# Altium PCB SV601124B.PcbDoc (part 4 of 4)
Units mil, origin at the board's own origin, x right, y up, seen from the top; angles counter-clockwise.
Board outline 3733 x 2734 mil, 4 copper layers (Top Layer, Mid-Layer 1, Mid-Layer 2, Bottom Layer), stack 60.2 mil thick; 246 components, 169 nets, 780 pads, 426 vias.
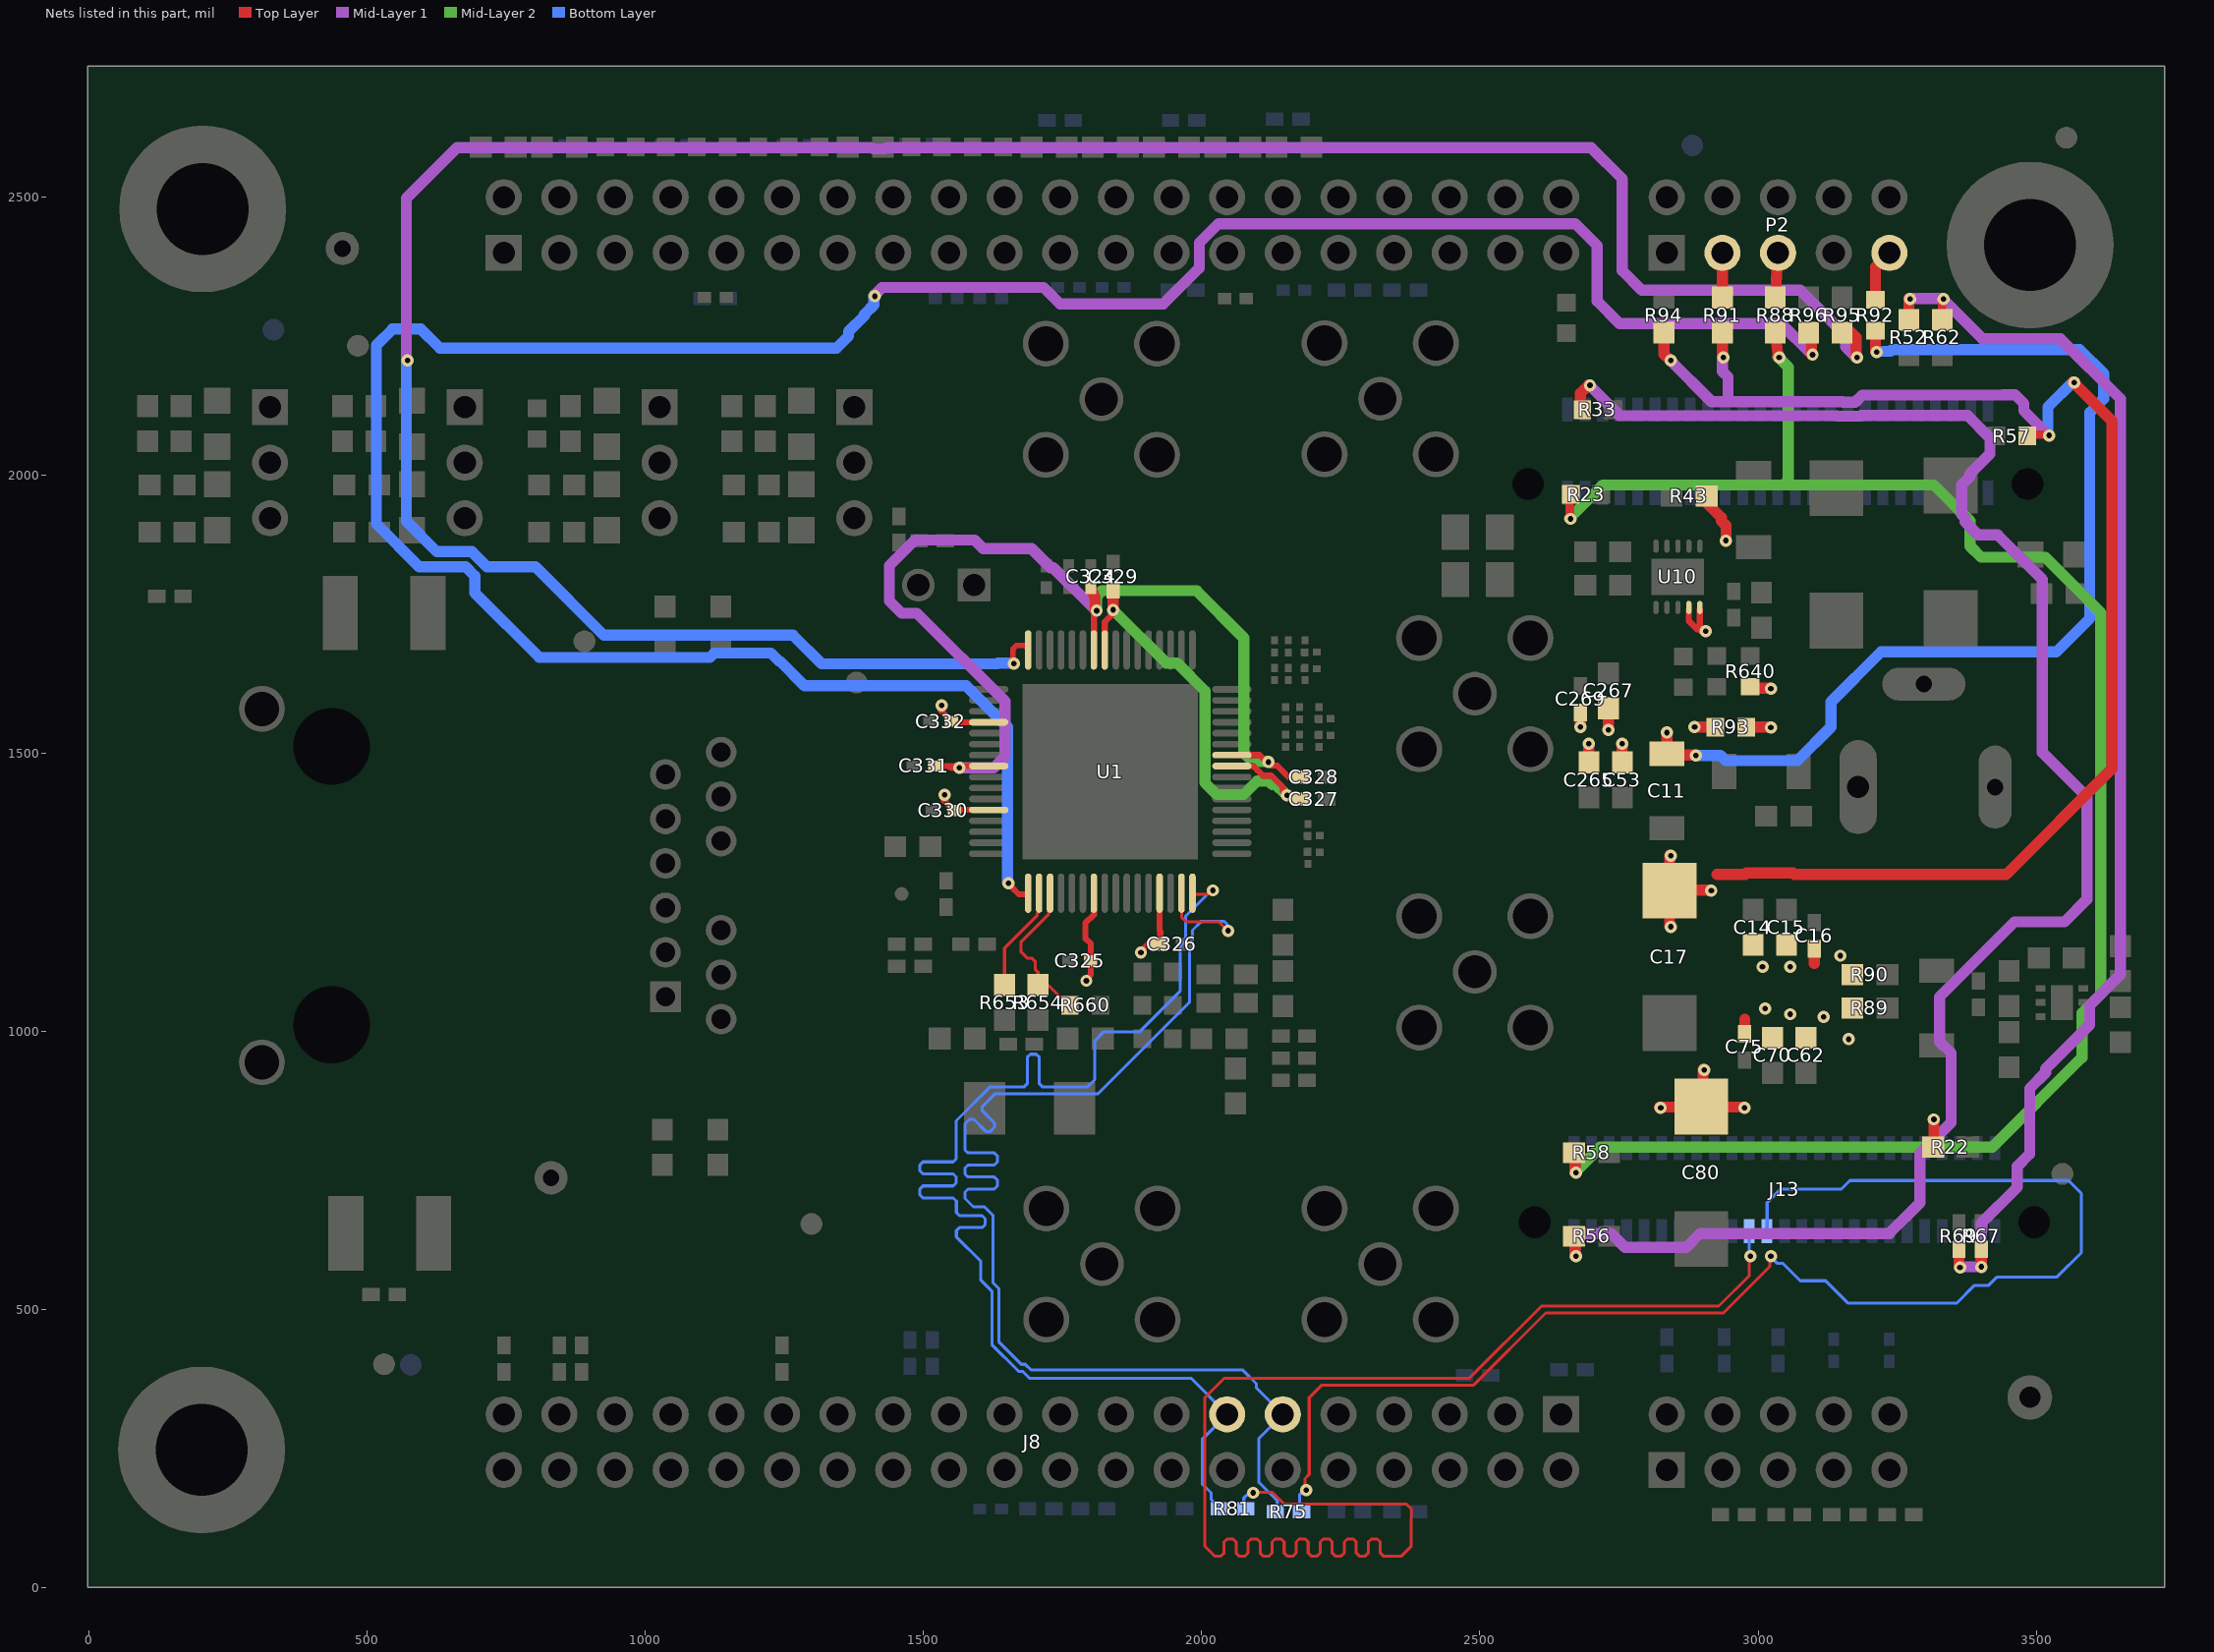
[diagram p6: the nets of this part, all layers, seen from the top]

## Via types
v1: diameter 22, hole 10, Top Layer to Bottom Layer, 385 vias
v2: diameter 19.68, hole 7.87, Top Layer to Bottom Layer, 40 vias
v3: diameter 20, hole 10, Top Layer to Bottom Layer, 1 vias

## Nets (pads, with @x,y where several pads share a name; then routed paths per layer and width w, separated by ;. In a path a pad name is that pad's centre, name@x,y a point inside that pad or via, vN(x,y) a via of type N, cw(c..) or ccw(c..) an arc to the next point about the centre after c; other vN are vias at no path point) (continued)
TXD6: J8.13 R81.1 U1.32 | length 2320.9
  Top Layer w5.4: U1.32@1983.6,1246.46 2010.46,1246.46 v1@2018.46,1254.46
  Bottom Layer w5.4: v1@2018.46,1254.46 1971.3,1207.3 1971.3,1162.86 1961.3,1152.86 1961.3,1072.14 1888.56,999.4 1824.44,999.4 1808.04,983 1808.04,913.26 1795.38,900.6 1713.79,900.6 1708.39,906 1708.39,953.6 1702.99,959 1692.19,959 1686.79,953.6 1686.79,906 1681.39,900.6 1620.38,900.6 1559,839.22 1559,771 1553.6,765.6 1499.4,765.6 1494,760.2 1494,749.4 1499.4,744 1553.6,744 1559,738.6 1559,727.8 1553.6,722.4 1499.4,722.4 1494,717 1494,706.2 1499.4,700.8 1553.6,700.8 1559,695.4 1559.4,695.4 1559.4,674.48 1564.8,669.08 1605.6,669.08 1611,663.68 1611,652.88 1605.6,647.48 1564.8,647.48 1559.4,642.08 1559.4,630.68 1603.4,586.68 1603.4,552.98 1623.1,533.28 1623.1,437.44 1671.11,389.43 1678.09,389.43 1690.49,377.03 1980.97,377.03 J8.13@2046,312 2001,267 2001,187 2017.14,170.86 2017.14,158.86 2034,142 R81.1@2036,142
  other v1: 2020.46,1253.46
TXD6_EMB: J13.30 R81.2 | length 2545.7
  Top Layer w5.4: v1@2091,172 2127,172 2148.34,150.66 2368.46,150.66 2377,142.12 2377,75 2359.4,57.4 2326.6,57.4 2321.2,62.8 2321.2,82.6 2315.8,88 2305,88 2299.6,82.6 2299.6,62.8 2294.2,57.4 2283.4,57.4 2278,62.8 2278,82.6 2272.6,88 2261.8,88 2256.4,82.6 2256.4,62.8 2251,57.4 2240.2,57.4 2234.8,62.8 2234.8,82.6 2229.4,88 2218.6,88 2213.2,82.6 2213.2,62.8 2207.8,57.4 2197,57.4 2191.6,62.8 2191.6,82.6 2186.2,88 2175.4,88 2170,82.6 2170,62.8 2164.6,57.4 2153.8,57.4 2148.4,62.8 2148.4,82.6 2143,88 2132.2,88 2126.8,82.6 2126.8,62.8 2121.4,57.4 2110.6,57.4 2105.2,62.8 2105.2,82.6 2099.8,88 2089,88 2083.6,82.6 2083.6,62.8 2078.2,57.4 2067.4,57.4 2062,62.8 2062,82.6 2056.6,88 2045.8,88 2040.4,82.6 2040.4,62.8 2035,57.4 2023.6,57.4 2005.77,75.23 2005.77,341.77 2041.03,377.03 2481.42,377.03 2610.89,506.5 2929.5,506.5 2984.36,561.36 v1@2984.36,597
  Bottom Layer w5.4: R81.2@2076,142 2076,161.7 2086.3,172 v1@2091,172 ; v1@2984.36,597 J13.30@2984.36,640.8
  other v1: 2093,171 2986.36,596
TXD7: J8.11 R75.1 U1.31 | length 2321
  Top Layer w5.4: U1.31@1963.92,1246.46 1963.92,1205.4 1972.32,1197 2031,1197 v1@2046,1182
  Bottom Layer w5.4: v1@2046,1182 2046,1192.62 2041,1197.62 1999.32,1197.62 1983.7,1182 1983.7,1151.17 1978.46,1145.93 1978.46,1052.46 1814.2,888.2 1629.2,888.2 1606,865 1606,857.38 1627.88,835.5 1627.88,827.88 1620.22,820.22 1612.6,820.22 1590.72,842.1 1583.1,842.1 1575,834 1575,787 1580.4,781.6 1627.6,781.6 1633,776.2 1633,765.4 1627.6,760 1580.4,760 1575,754.6 1575,743.8 1580.4,738.4 1627.6,738.4 1633,733 1633,722.2 1627.6,716.8 1580.4,716.8 1575,711.4 1575,700 1590,685 1610,685 1625,670 1625,548.92 1635.5,538.42 1635.5,442.58 1676.25,401.83 1683.23,401.83 1693.06,392 2073.54,392 2098.63,366.91 2098.63,359.37 J8.11@2146,312 2103.14,269.14 2103.14,189.56 2136,156.7 R75.1@2136,137
  other v1: 2048,1181
TXD7_EMB: J13.28 R75.2 | length 2538.9
  Top Layer w5.4: v1@2186,177 2186,196.7 2193.37,204.07 2193.37,341.91 2216.09,364.63 2489.13,364.63 2618.6,494.1 2937.8,494.1 3021,577.3 v1@3021,597
  Bottom Layer w5.4: R75.2@2176,137 2176,167 v1@2186,177 ; J13.28@3016.36,640.8 3016.36,692.36 3041,717 3150,717 3165.08,732.08 3557.92,732.08 3581,709 3581,602.46 3537.44,558.9 3429.72,558.9 3414.72,543.9 3389.12,543.9 3356.62,511.4 3162.14,511.4 3121.54,552 3076,552 3044.94,583.06 3034.94,583.06 v1@3021,597
  other v1: 2188,176 3023,596
UN-USED_SUPPLY_3V3: R33.2 R56.1 | length 3248.7
  Top Layer w20: v1@2671,597 R56.1@2671,632 ; R33.2@2681,2117 2681,2147 v1@2696,2162
  Mid-Layer 1 w20: v1@2671,597 2671,627 2681,637 2736,637 2761,612 2871,612 2896,637 3236,637 3291,692 3291,780.22 3347,836.22 3347,961 3326,982 3326,1062 3461,1197 3550.64,1197 3591,1237.36 3591,1421 3511,1501 3511,1812 3431,1892 3396,1892 3372,1916 3372,1922.78 3366,1928.78 3366,1982 3381,1997 3381,2002 3416.86,2037.86 3416.86,2066.14 3376,2107 3186.12,2107 3184.67,2105.55 3142.43,2105.55 3141.43,2106.55 2935.64,2106.55 2751.45,2106.55 v1@2696,2162
  other v1: 2673,596 2698,2161
VDD1P1: R52.2 R62.2 R67.1 R69.1 | length 2306.6
  Top Layer w15: R62.2@3331,2277 v1@3331,2317
  Top Layer w20: R52.2@3271,2278.5 v1@3271,2317 ; v1@3361,577 R69.1@3361,612 ; v1(3401,577) R67.1@3401,612
  Mid-Layer 1 w20: v1@3271,2317 3331,2317 3403.29,2244.71 3543.29,2244.71 3651,2137 3651,1102 3596,1047 3596,1012 3517,933 3517,926.22 3488.2,897.42 3488.2,780.02 3466,757.82 3466,720.22 3401,655.22 v1(3401,577) v1@3361,577
  other v1: 3363,576 3273,2316 3333,2316
VDDA1P8_AB: R95.1 U1.64 | length 4806.5
  Top Layer w10: v1@1661,1662 1661,1687 1667.89,1693.89 1682.05,1693.89 U1.64@1688.4,1687.54
  Top Layer w20: R95.1@3151,2257 3166,2257 3176,2247 v1@3176,2212
  Mid-Layer 1 w20: v1@571,2207 571,2497 662,2588 1404.55,2588 1408.16,2587.43 1411.86,2586.07 1412.46,2585.7 1429.44,2585.7 1433.08,2587.21 1436.94,2587.98 2700,2587.98 2755.98,2532 2755.98,2367 2790.99,2331.99 3075.99,2331.99 3157.61,2250.37 3157.61,2230.39 v1@3176,2212
  Bottom Layer w20: v1@571,2207 571,1917 625.99,1862 688.79,1862 715.79,1835 803,1835 926,1712 1266,1712 1317.56,1660.44 1632.44,1660.44 1634,1662 v1@1661,1662
  other v1: 1663,1661 573,2206 3178,2211
VDDA1P8_CD: R96.1 U1.17 | length 4919
  Top Layer w10: 1663.54,1254.46 1671.54,1246.46 U1.17@1688.4,1246.46
  Top Layer w11: v1@1651,1267 1663.54,1254.46
  Top Layer w20: R96.1@3091,2257 3095.29,2252.71 3096,2247 v1@3096,2217
  Mid-Layer 1 w20: v1@1411,2322 1426,2337 1716,2337 1746,2307 1931,2307 1996,2372 1996,2417 2030.47,2451.47 2671.53,2451.47 2711,2412 2711,2312 2751,2272 3041,2272 v1@3096,2217
  Bottom Layer w20: v1@1411,2322 1411,2305.5 1394.5,2289 1394.5,2286.5 1365.7,2257.7 1365.7,2249.53 1344.17,2228 631,2228 597,2262 546,2262 517,2233 517,1912 594,1835 677.6,1835 694,1818.6 694,1788 810,1672 1116.4,1672 1124.4,1680 1226,1680 1241,1665 1242.6,1665 1286.6,1621 1577,1621 1651,1547 v1@1651,1267
  other v1: 1653,1266 3098,2216 1413,2321
VDDA1V1: C11.1 C53.1 C265.2 C267.2 C269.2 C324.2 C326.2 C328.2 C331.2 R92.1 R93.2 U1.8 U1.29 U1.42 U1.58 | length 4085.3
  Top Layer w11: C331.2@1521,1477 1545.5,1477 ; v1@1566,1473.55 v1(1564.45,1473.55) 1561,1477 1545.5,1477 ; U1.8@1615.46,1476.84 1574.39,1476.84 1573.21,1475.66 1572.9,1475.66 1570.74,1473.5 1551.26,1473.5 1549.1,1475.66 1546.84,1475.66 1545.5,1477 ; U1.58@1806.48,1687.54 1806.48,1753.98 v1@1809.5,1757 ; v1@1891,1143 1891,1144.6 1903.4,1157 1926,1157 1926,1179.5 1924.56,1180.94 U1.29@1924.56,1246.46 ; U1.42@2056.54,1496.52 2104.19,1496.52 2115.72,1484.99 2117.84,1484.99 2125.26,1477.57 2135.93,1477.57 2156.5,1457 C328.2@2181,1457
  Top Layer w20: C324.2@1801,1797 1807.89,1780.94 1807.89,1761.61 1809.5,1760 v1@1809.5,1757 ; v1(2681,1547) C269.2@2681,1577 ; C265.2@2696,1482 v1(2696,1517) ; v1(2731,1542) C267.2@2731,1582 ; C53.1@2756,1482 v1(2756,1517) ; C11.1@2836,1498.93 v1(2836,1537) ; C11.1@2837.93,1497 v1@2886,1497 ; v1(2886,1547) R93.2@2921,1547 ; v1@3211,2222 R92.1@3211,2257
  Mid-Layer 1 w20: v1@1566,1473.55 1626.55,1473.55 1647,1494 1647,1592.84 1488.32,1751.52 1461,1751.52 1439,1773.52 1439,1837 1485,1883 1592,1883 1607.5,1867.5 1694.5,1867.5 1729,1833 1733.5,1833 v1@1809.5,1757
  Mid-Layer 2 w20: v1@1809.5,1757 1811,1758.5 1811,1782 1821,1792 1991,1792 2076,1707 2076,1500.83 2091.84,1484.99 v1@2117.84,1484.99
  Bottom Layer w20: v1(2888,1496) 2932.48,1496 2942,1486.48 3070.48,1486.48 3131,1547 3131,1592 3221,1682 3536,1682 3596,1742 3596,2112 3621,2137 3621,2182 3578,2225 3241,2225 3238,2222 v1@3211,2222
  other v1: 1891,1142 2119.84,1483.99 1811.5,1756 3213,2221
VDDA2P5: C62.2 C70.2 C75.2 C80.1 C330.2 C332.2 R23.1 R58.2 R88.1 R89.2 U1.4 U1.12 | length 3727.4
  Top Layer w11: v1@1531,1587 1531,1577 1551,1557 1552.44,1555.56 U1.4@1615.46,1555.56 ; v1@1536,1426.42 1536,1416.68 1549.18,1403.5 1549.5,1403.5 1556,1397 1557.12,1398.12 U1.12@1615.46,1398.12
  Top Layer w15: v1@2661,1922 R23.1@2661,1967
  Top Layer w20: v1@2671,747 R58.2@2671,782 ; v1@2823.01,864.01 C80.1@2901,864.01 ; v1@2901,932 C80.1@2901,864.01 ; v1@2973.99,864.01 C80.1@2901,864.01 ; C75.2@2976,992 2976,1022 ; R88.1@3031,2257 v1@3036,2212
  Mid-Layer 2 w20: v1@2661,1922 2721,1982 3046,1982 ; v1@2671,747 2716,792 3421,792 3582,953 3582,1033 3616,1067 3616,1752 3516,1852 3401,1852 3381,1872 3381,1917 3316,1982 3046,1982 ; v1@3036,2212 3054.39,2193.61 3054.39,1990.39 3046,1982
  other v1: 2673,746 2825.01,863.01 2975.99,863.01 2903,931 3163,986 3118,1026 3058,1031 3013,1041 1538,1425.42 1533,1586 2663,1921 3038,2211
VDDA2P5_EXT: P2.5 R88.2 | length 82.2
  Top Layer w20: R88.2@3031,2317 P2.5@3036,2399
VDDA_1V1_DUT: R43.1 R93.1 R640.2 U10.9 U10.10 | length 267.7
  Top Layer w11: U10.9@2875.69,1757.94 2875.69,1737.31 2890.5,1722.5 2893.64,1722.5 2896.18,1719.96 2903.96,1719.96 2895.37,1728.55 U10.10@2895.37,1757.94
  Top Layer w20: R43.1@2906,1962 2906,1951.6 2934,1923.6 2934,1917.44 2942.44,1909 v1(2942.44,1882) ; R93.1@2981,1547 v1@3021,1547 ; R640.2@2986,1617 v1@3021,1617
  other v1: 3023,1546 3023,1616 2905.96,1718.96
VDDA_1V1_EXT: P2.9 R92.2 | length 92.4
  Top Layer w20: R92.2@3211,2317 3211,2374 P2.9@3236,2399
VDDIO: C14.2 C15.2 C16.2 C17.1 C325.2 C327.2 C329.2 R22.1 R57.2 R90.1 R91.2 R94.2 U1.23 U1.41 U1.57 | length 3886.2
  Top Layer w11: v1@1791,1092 1801,1102 1801,1157.31 1791.15,1167.16 1791.15,1194.6 1806.48,1209.93 U1.23@1806.48,1246.46 ; U1.57@1826.16,1687.54 1826.16,1735.8 1841.5,1751.14 v1@1841.5,1757 ; U1.41@2056.54,1476.84 2092.79,1476.84 2100.4,1469.23 ; 2100.4,1469.19 2110.02,1459.57 2125.29,1459.57 2146.31,1438.55 2146.31,1430.99 2151.81,1425.49 2152.52,1424.78 2153.22,1424.78 2161,1417 C327.2@2181,1417
  Top Layer w15: R57.2@3486,2072 v1@3521,2072
  Top Layer w20: C329.2@1841,1797 v1(1841,1757.5) v1@1841.5,1757 ; R94.2@2831,2257 2831,2217 v1@2841,2207 ; v1@2841,1189 C17.1@2841,1254.01 ; v1@2841,1317 C17.1@2841,1254.01 ; v1@2913.99,1254.01 C17.1@2841,1254.01 ; 2926,1282 2976.4,1282 2979.4,1285 3062.6,1285 3065.6,1282 3446,1282 3636,1472 3636,2097 v1@3566,2167 ; v1@2936,2212 R91.2@2936,2257 ; 3101,1122 C16.2@3101,1152 ; R22.1@3316,792 v1(3316,842)
  Mid-Layer 1 w20: v1@2841,2207 2916.45,2131.55 2946,2131.55 ; v1@2936,2212 2936,2186 2946,2176 2946,2131.55 ; v1@3521,2072 3477.58,2115.42 3477.58,2128.36 3462.36,2143.58 3462.19,2143.58 3461.77,2144 3440.23,2144 3439.81,2143.58 3187.35,2143.58 3174.32,2130.55 3152.78,2130.55 3151.78,2131.55 2946,2131.55
  Mid-Layer 2 w20: v1@1841.5,1757 1936.5,1662 1956,1662 2006,1612 2006,1447 2027.51,1425.49 2075.45,1425.49 2099.63,1449.67 2121.19,1449.67 2126.98,1443.88 2133.42,1443.88 v1@2151.81,1425.49
  Bottom Layer w20: v1@3521,2072 3521,2122 v1@3566,2167
  other v1: 1793,1091 3008,1116 3058,1116 3148,1136 2843,1188 2915.99,1253.01 2843,1316 2153.81,1424.49 3523,2071 3568,2166 2843,2206 2938,2211
VDDIO_EXT: P2.3 R91.1 | length 82
  Top Layer w20: R91.1@2936,2317 P2.3@2936,2399
XI: R654.2 R660.1 U1.19 | length 273.1
  Top Layer w5.4: U1.19@1727.76,1246.46 1727.76,1217.58 1724.67,1214.49 1724.67,1209.95 1675.3,1160.58 1675.3,1143.42 1687.42,1131.3 1695.5,1131.3 1700.9,1125.9 1700.9,1111.8 1706,1106.7 1706,1082 1726,1082 R660.1@1761,1047
XO: R653.2 U1.18 | length 190.2
  Top Layer w5.4: R653.2@1646,1082 1646,1149.95 1704.99,1208.94 1704.99,1212.35 1708.08,1215.44 U1.18@1708.08,1246.46
pads on no net: FID1.1 FID2.1 FID3.1 FID4.1 FID5.1 FID6.1 FID7.1 FID8.1 FID9.1 FID10.1 J1.MH1 J1.MH2 J8.3 J8.27 J8.31 J8.35 J9.35 J11.18 J11.20 J11.22 J11.24 J11.28 J11.29 J11.30 J11.32 J11.34 J11.36 J11.38 J11.39 J11.40 J11.41 J11.42 J11.MH1 J11.MH2 J13.8 J13.12 J13.13 J13.15 J13.17 J13.21 J13.22 J13.23 J13.24 J13.27 J13.29 J13.MH1 J13.MH2 LBL1.0 U1.1 U1.7 U1.9 U2.5
copper on no net: | length 1300
  Top Layer w8: 21,552 121,552 ; 21,652 121,652 ; 21,752 121,752 ; 21,452 121,452 121,852 21,852 21,452

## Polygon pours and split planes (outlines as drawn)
VDDA2P5 on Top Layer "TOP-VDDA2V5" (solid, pour order 74): 54 vertices, not listed, extent 2941,962 3206,1072
NetC13_1 on Top Layer "TOP-UNNAMED_1_CAPACITOR_I156_B" (solid, pour order 82): 38 vertices, not listed, extent 3211,1022 3521,1147
VDDIO on Top Layer "TOP-IOVDD" (solid, pour order 88): 79 vertices, not listed, extent 2716,1088.86 3191,1327
GND on Top Layer "TOP-GND_POWER" (solid, pour order 100): 448 vertices, not listed, extent 1459.16,426.94 1980.28,743.84
GND on Top Layer "TOP-GND_POWER 1" (solid, pour order 102): 616 vertices, not listed, extent 2155.78,426.94 2816,887.94
GND on Top Layer "TOP-GND_POWER 2" (solid, pour order 104): 487 vertices, not listed, extent 1779.44,2471.48 2034.37,2661.88
GND on Top Layer "TOP-GND_POWER 3" (solid, pour order 106): 546 vertices, not listed, extent 568.72,2406.77 1818.23,2674.28
GND on Top Layer "TOP-GND_POWER 4" (solid, pour order 108): 1183 vertices, not listed, extent 2181,2149.56 3458.28,2649.48
GND on Top Layer "TOP-GND_POWER 5" (solid, pour order 110): 517 vertices, not listed, extent 3181,2149.56 3648.28,2609.86
GND on Top Layer "TOP-GND_POWER 6" (solid, pour order 112): 117 vertices, not listed, extent 1314.52,1944.02 1473.93,2102
GND on Top Layer "TOP-GND_POWER 7" (solid, pour order 114): 297 vertices, not listed, extent 961,1779.77 1413.28,2176.58
GND on Top Layer "TOP-GND_POWER 8" (solid, pour order 116): 336 vertices, not listed, extent 16,1762 2183.29,2712
GND on Top Layer "TOP-GND_POWER 9" (solid, pour order 118): 689 vertices, not listed, extent 1494.54,1630.12 2299.01,2357
GND on Top Layer "TOP-GND_POWER 10" (solid, pour order 120): 996 vertices, not listed, extent 1407.53,843.28 2283.94,1709.28
GND on Top Layer "TOP-GND_POWER 11" (solid, pour order 122): 157 vertices, not listed, extent 1708.72,816.56 2173.45,1002
GND on Top Layer "TOP-GND_POWER 12" (solid, pour order 124): 5398 vertices, not listed, extent 586,22 3706,2712
GND on Top Layer "TOP-GND_POWER 13" (solid, pour order 126): 39 vertices, not listed, extent 588.72,2214.42 686,2386.28
GND on Top Layer "TOP-GND_POWER 14" (solid, pour order 128): 139 vertices, not listed, extent 1410.86,1543.66 1521.99,1673.84
GND on Top Layer "TOP-GND_POWER 15" (solid, pour order 130): 136 vertices, not listed, extent 1184.16,1382 1422.9,1673.84
GND on Top Layer "TOP-GND_POWER 16" (solid, pour order 132): 70 vertices, not listed, extent 3005.87,670.7 3259.14,758.62
GND on Top Layer "TOP-GND_POWER 17" (solid, pour order 134): 246 vertices, not listed, extent 3097.72,2457.72 3309.77,2582.28
GND on Top Layer "TOP-GND_POWER 18" (solid, pour order 136): 392 vertices, not listed, extent 2018.48,207 2190.72,364.32
ERTH_GND on Top Layer "TOP-GND_EARTH" (solid, pour order 180): 653 vertices, not listed, extent 16,22 496,1837
VDDA2P5 on Mid-Layer 1 "L2-PWR-SIG-VDDA2V5" (solid, pour order 72): 1510 vertices, not listed, extent 974,632.02 3326.98,1709
VDDA1V1 on Mid-Layer 1 "L2-PWR-SIG-VDDA1V1" (solid, pour order 78): 1370 vertices, not listed, extent 1816,1142.02 3025.98,1766.98
AUX_IOVDD on Mid-Layer 1 "L2-PWR-SIG-AUX_IOVDD" (solid, pour order 84): 8199 vertices, not listed, extent 46,52 3676,2697
VDDIO on Mid-Layer 1 "L2-PWR-SIG-IOVDD" (solid, pour order 86): 1081 vertices, not listed, extent 1691,1022 3406,1462
ERTH_GND on Mid-Layer 1 "L2-PWR-SIG-GND_EARTH" (solid, pour order 176): 416 vertices, not listed, extent 16,22 496,1837
5V_SUPPLY on Mid-Layer 1 "L2-PWR-SIG-5V_SUPPLY" (solid, pour order 184): 542 vertices, not listed, extent 2506,1202 3570.98,2082
GND on Mid-Layer 2 "L3-GND-GND_POWER" (solid, pour order 138): 63 vertices, not listed, extent 16,22 3706,2712
ERTH_GND on Mid-Layer 2 "L3-GND-GND_EARTH" (solid, pour order 178): 416 vertices, not listed, extent 16,22 496,1837
VDDA_1V1_DUT on Bottom Layer "BOTTOM-VDDA_1V1_DUT" (solid, pour order 70): 292 vertices, not listed, extent 2866,1522 3086,1907
VDDA2P5 on Bottom Layer "BOTTOM-VDDA2V5" (solid, pour order 76): 3126,1062 3146,1062 3201,1007 3201,892 3136,827 2836,827 2806,857 2806,982 2881,1057 3121,1057 3126,1062
VDD1P1 on Bottom Layer "BOTTOM-VDDA1V1" (solid, pour order 80): 213 vertices, not listed, extent 2641,1457 2936,1587
VDDIO on Bottom Layer "BOTTOM-IOVDD" (solid, pour order 90): 136 vertices, not listed, extent 2812,827 3351,1342
GND on Bottom Layer "BOTTOM-GND_POWER" (solid, pour order 92): 1055 vertices, not listed, extent 718.48,76.92 1354.65,489.28
GND on Bottom Layer "BOTTOM-GND_POWER 1" (solid, pour order 94): 66 vertices, not listed, extent 2701.19,64.52 2877.08,241.43
GND on Bottom Layer "BOTTOM-GND_POWER 2" (solid, pour order 96): 543 vertices, not listed, extent 2879.97,52.12 3123.28,409.72
GND on Bottom Layer "BOTTOM-GND_POWER 3" (solid, pour order 98): 798 vertices, not listed, extent 2313.51,2145.79 3300.28,2643.58
GND on Bottom Layer "BOTTOM-GND_POWER 4" (solid, pour order 140): 389 vertices, not listed, extent 3340.52,1997.75 3533.28,2204.98
GND on Bottom Layer "BOTTOM-GND_POWER 5" (solid, pour order 142): 1333 vertices, not listed, extent 16,1762 1494.64,2712
GND on Bottom Layer "BOTTOM-GND_POWER 6" (solid, pour order 144): 322 vertices, not listed, extent 1918.01,1481.21 2223.94,1897.97
GND on Bottom Layer "BOTTOM-GND_POWER 7" (solid, pour order 146): 257 vertices, not listed, extent 2108.76,1378.15 2307.78,1503.48
GND on Bottom Layer "BOTTOM-GND_POWER 8" (solid, pour order 148): 3160 vertices, not listed, extent 1574.16,1292.16 3600.98,2426.52
GND on Bottom Layer "BOTTOM-GND_POWER 9" (solid, pour order 150): 952 vertices, not listed, extent 537.02,1209.83 2089.23,2241.98
GND on Bottom Layer "BOTTOM-GND_POWER 10" (solid, pour order 152): 382 vertices, not listed, extent 2968.77,698.3 3259.51,762.96
GND on Bottom Layer "BOTTOM-GND_POWER 11" (solid, pour order 154): 1897 vertices, not listed, extent 1673.02,126.52 2685.92,1316.88
GND on Bottom Layer "BOTTOM-GND_POWER 12" (solid, pour order 156): 2869 vertices, not listed, extent 1516.05,22 3706,2712
GND on Bottom Layer "BOTTOM-GND_POWER 13" (solid, pour order 158): 167 vertices, not listed, extent 1121.72,2547.54 1283.28,2663.28
GND on Bottom Layer "BOTTOM-GND_POWER 14" (solid, pour order 160): 128 vertices, not listed, extent 2822.99,2145.42 3053.84,2296.88
GND on Bottom Layer "BOTTOM-GND_POWER 15" (solid, pour order 162): 393 vertices, not listed, extent 2550.16,2093.16 2826.85,2365.81
GND on Bottom Layer "BOTTOM-GND_POWER 16" (solid, pour order 164): 156 vertices, not listed, extent 1953.3,1768.3 2363.94,1975.34
GND on Bottom Layer "BOTTOM-GND_POWER 17" (solid, pour order 166): 36 vertices, not listed, extent 714.02,1737 865.63,1814.98
GND on Bottom Layer "BOTTOM-GND_POWER 18" (solid, pour order 168): 673.98,1779.71 733.85,1719.85 696,1682 621,1682 616,1677 596,1677 586,1687 586,1814.98 669.31,1814.98 673.98,1810.31 673.98,1779.71
GND on Bottom Layer "BOTTOM-GND_POWER 19" (solid, pour order 170): 602 vertices, not listed, extent 1493.02,964.4 1898.98,1194.78
GND on Bottom Layer "BOTTOM-GND_POWER 20" (solid, pour order 172): 111 vertices, not listed, extent 3403.09,761.23 3660.28,850.28
GND on Bottom Layer "BOTTOM-GND_POWER 21" (solid, pour order 174): 483 vertices, not listed, extent 631,22 1631.41,1659.98
ERTH_GND on Bottom Layer "BOTTOM-GND_EARTH" (solid, pour order 182): 417 vertices, not listed, extent 16,22 496,1837

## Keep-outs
Keep-Out Layer:
  text ".Layer_Name" at 575,-857.49 h60

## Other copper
Top Layer:
  drawing of 181 lines, arcs and shapes, not listed
  text "1" at 51,777 h50
  text "CS" at 452,47 h80
  text ".Layer_Name" at 575,-857.49 h60
Mid-Layer 1:
  drawing of 281 lines, arcs and shapes, not listed
  text "2" at 51,677 h50
Mid-Layer 2:
  drawing of 322 lines, arcs and shapes, not listed
  text "3" at 51,577 h50
Bottom Layer:
  drawing of 97 lines, arcs and shapes, not listed
  text "4" at 51,477 h50
  text "PS" at 452,47 h80
  text ".Layer_Name" at 575,-857.49 h60

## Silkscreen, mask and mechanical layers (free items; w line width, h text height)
Top Overlay:
  lines w6: 895,2636.01 895,2721.01 ; 1115,2636.01 1115,2721.01 ; 1335,2636.01 1335,2721.01 ; 1555,2636.01 1555,2721.01 ; 1775,2636.01 1775,2721.01 ; 1950,2342 1980,2312 1980,2297 ; 1959.7,1782.58 1959.7,1943.58 ; 1995,2636.01 1995,2721.01 ; 2241.99,1158 2351.99,1158 ; 2346,353 2346,408 2636,408 2636,458 3101,458 3101,478 ; 2446,353 2446,408 ; 2541,353 2541,408 ; 2781,458 2781,478 ; 2941,458 2941,483 ; 3227,2214.01 3227,2184.01 3252,2159.01 3262,2159.01
  text "6" at 1679,2707.01 h30 r90
  text "5" at 1898,2705.01 h30 r90
  text "PD  PU" at 701,2681.01 h35
  text "PD  PU" at 921,2681.01 h35
  text "PD  PU" at 1141,2681.01 h35
  text "RX_" at 1204,2681.01 h30
  text "PD  PU" at 1361,2681.01 h35
  text "RX_" at 1424,2681.01 h30
  text "PD  PU" at 1581,2681.01 h35
  text "PD  PU" at 1801,2681.01 h35
  text "PD  PU" at 2021,2681.01 h35
  text "4 LEVEL STRAP" at 2298,2681.01 h35
  text "4" at 2197,2638.01 h30
  text "CS" at 761,2636.01 h30
  text "COL" at 969,2636.01 h30
  text "ER" at 1201,2636.01 h30
  text "DV" at 1421,2636.01 h30
  text "RXD" at 2114,2636.01 h30
  text "RESISTORS" at 2304,2626.01 h35
  text "EXT POWER SUPPLIES" at 2814,2624.01 h35
  text "RXD" at 1680,2623.01 h30 r90
  text "RXD" at 1900,2623.01 h30 r90.1
  text "40" at 2624,2563 h30
  text "GND" at 598,2498 h30
  text "GMII CON" at 551.99,2383 h35 r90
  text "39" at 2736,2369 h30 r90
  text "CS" at 724,2309 h30
  text "COL" at 812,2309 h30
  text "RX_" at 912,2309 h30
  text "RX_" at 1012,2309 h30
  text "RX6" at 1205,2309 h30
  text "RX5" at 1305,2309 h30
  text "RX4" at 1405,2309 h30
  text "RX3" at 1505,2309 h30
  text "RX2" at 1605,2309 h30
  text "RX1" at 1705,2309 h30
  text "RX0" at 1805,2309 h30
  text "LED0" at 2097,2309 h30
  text "LED1" at 2200,2309 h30
  text "LED2" at 2299,2308 h30
  text "EXT" at 2674,2307 h30
  text "RXD" at 1112,2267 h30
  text "DV" at 1009,2264 h30
  text "ER" at 909,2262 h30
  text "CLK" at 2674,2262 h30
  text "EXT" at 2519,2232 h30 r90
  text "7" at 1121,2222 h30
  text "PWDN" at 2053,2196 h30 r90
  text "LNK100" at 92,2186.01 h35
  text "ACT" at 529,2181.01 h35
  text "LNK1G" at 816,2181.01 h35
  text "LINK" at 1185,2181.01 h35
  text "EXT" at 2801,2174.01 h30
  text "EXT" at 2901,2174.01 h30
  text "RESET_N" at 2562,2168 h30 r90
  text "EXT VDD" at 3283,2144.01 h30
  text "RX_CLK" at 2001,2131 h30 r90
  text "IOVDD" at 2877,2129.01 h30
  text "AUX" at 2786,2128.01 h30
  text "VDDA" at 3084,2115.01 h30 r90
  text "VDDA" at 3170,2114.01 h30 r90
  text "RXD2" at 2506,2088 h35 r90
  text "IOVDD" at 2797,2084.01 h30
  text "SGMII" at 1975,2077 h35
  text "1P8_AB" at 3125,2065.01 h30 r90
  text "1P8_CD" at 3218,2059.01 h30 r90
  text "SO" at 1972,2027 h35
  text "EXT VDDA" at 3042.51,2019.2 h30 r90
  text "5V LED" at 3513,1985.01 h35
  text "RXD3" at 1904.7,1892.7 h25 r90
  text "STRAP" at 1943.7,1885.58 h25 r90
  text "LED2" at 430.6,1830.92 h35
  text "LED1" at 1200,1831.01 h35
  text "RXD7" at 157,1820 h35
  text "LED0" at 809,1820 h35
  text "RXD2" at 1904.7,1782.58 h25 r90
  text "STRAP" at 1944.7,1762.58 h25 r90
  text "VDD" at 2754,1735 h30
  text "64" at 1578,1702 h30
  text "RESET_N" at 1323,1700.01 h35
  text "LDO" at 2755,1698 h30
  text "1" at 1585,1648 h30
  text "5V JACK" at 3459,1644.01 h35
  text "RXD1" at 2407,1368.01 h35
  text "SGMII" at 2501,1310 h35
  text "33" at 2053,1277 h30
  text "CO" at 2530,1268.01 h35
  text "RXD0" at 2402,1243.01 h35
  text "32" at 2005,1232 h30
  text "RXD1" at 2286.99,1170 h30 r90
  text "STRAP" at 2342.99,1166 h30 r90
  text "OSC" at 2020.8,1141.35 h35
  text "RXD0" at 2288.99,1031 h30 r90
  text "STRAP" at 2343.99,1025 h30 r90
  text "2.5V" at 3507,881.01 h35
  text "LDO" at 3510,833.01 h35
  text "TXD2" at 2194,745 h35
  text "TXD1" at 1553,648.01 h35
  text "SGMII" at 1995,648.01 h35
  text "SI" at 1992,598.01 h35
  text "CLKOUT" at 1192,498 h30 r90
  text "TX_CLK" at 2719,498 h30
  text "TX_ER" at 2881,498 h30
  text "CTX_CLK" at 3017,498 h30
  text "JTAG" at 2828,418 h30
  text "JTAG CONNECTOR" at 3033,418 h30
  text "TX_EN" at 2686,383 h30
  text "TX1" at 1514,379.01 h30
  text "TX0" at 1614,379.01 h30
  text "TX2" at 1714,379.01 h30
  text "TX3" at 1814,379.01 h30
  text "TX4" at 1914,379.01 h30
  text "TX5" at 2014,379.01 h30
  text "TX6" at 2114,379.01 h30
  text "TX7" at 2214,379.01 h30
  text "TRSTN" at 2831,378 h30
  text "TMS" at 2995,378 h30
  text "CLK" at 3095,378 h30
  text "TDO" at 3195,378 h30
  text "TDI" at 3295,378 h30
  text "GND" at 3315,190.01 h35
  text ".Layer_Name" at 575,-857.49 h60
Bottom Overlay:
  text "DP83867IRPAP-EVM" at 892,1915 h80 r90
  text "DP83867IRPAP 1G  Ethernet" at 205,1826 h80 r90
  text "SV601124B" at 1277.16,1744.28 h80 r90
  text ".Layer_Name" at 575,-857.49 h60
Top Paste:
  text ".Layer_Name" at 575,-857.49 h60
Bottom Paste:
  text ".Layer_Name" at 575,-857.49 h60
Top Solder:
  text ".Layer_Name" at 575,-857.49 h60
  text ".Layer_Name" at 575,-857.49 h60
Bottom Solder:
  text ".Layer_Name" at 575,-857.49 h60
Drill Guide:
  text ".Layer_Name" at 575,-857.49 h60
M1 Board Outline:
  lines w1: -2,2730.76 3728.71,2730.76 ; -2,2730.76 -2,1 3728.71,1 3728.71,2730.76 ; -2,2730.76 3728.71,2730.76
  lines w10: 0,0 0,2734 3733,2734 3733,0 0,0
  text ".Layer_Name" at 575,-857.49 h60
M2 Board Dimensions:
  lines w10: 4315.18,69.06 4335,9 ; 4322.82,2670.06 4343,2730 ; 4325,9.03 4345,8.97 ; 4333,2730.03 4353,2729.97 ; 4337.87,983.62 4335,9 ; 4340.13,1755.38 4343,2730 ; 4355.18,68.94 4335,9 ; 4362.82,2669.94 4343,2730
  text "2721.012 (mil)" at 4373.89,993.52 h60 r89.83
  text ".Layer_Name" at 575,-857.49 h60
M3 3D STEP Top:
  text ".Layer_Name" at 575,-857.49 h60
M4 3D STEP Bottom:
  text ".Layer_Name" at 575,-857.49 h60
M5 Assembly Top:
  lines w10: -294,-929.17 6306,-929.17 ; -294,-725.83 6308,-725.83 ; -294,-522.5 -294,-1132.5 3711,-1132.5 6308,-1132.5 6308,-522.5 ; -293.5,-522.5 -293.5,-1132.5 1282,-1132.5 ; 2171,-1132.5 2171,-522.5 ; 3438,-725.83 3438,-522.5 ; 4278,-725.83 4278,-522.5 ; 4900,-1139 4900,-936.17
  text "PCB VIEWED FROM TOP SIDE" at -230.5,-654.67 h60
  text "BOARD #:" at 2246,-654.67 h60
  text ".PRJ_Number" at 2791.5,-654.67 h60
  text "REV:" at 3636,-654.67 h60
  text ".PCB_Rev" at 3927.5,-654.67 h60
  text "SVN REV:" at 4474,-654.67 h60
  text ".VersionControl_RevNumber" at 4980,-654.67 h60
  text "PLOT NAME =" at -230.5,-1063.34 h60
  text ".plot_File_Name" at 575,-1063.34 h60
  text "GENERATED    :" at 2248,-1063.34 h60
  text ".Print_Date" at 3117.5,-1063.34 h60
  text ".Print_Time" at 3846.5,-1063.34 h60
  text "TEXAS INSTRUMENTS" at 5111,-1063.34 h60
M6 Assembly Bottom:
  lines w10: -294.5,-726.33 6307.5,-726.33 ; -294.5,-523 -294.5,-1133 2302.5,-1133 6307.5,-1133 6307.5,-523 ; -292.5,-929.67 6307.5,-929.67 ; 1113.5,-1139.5 1113.5,-936.67 ; 1735.5,-726.33 1735.5,-523 ; 2575.5,-726.33 2575.5,-523 ; 3842.5,-1133 3842.5,-523 ; 4731.5,-1133 6307,-1133 6307,-523
  text ".VersionControl_RevNumber" at 1033.5,-655.17 h60
  text "SVN REV:" at 1539.5,-655.17 h60
  text ".PCB_Rev" at 2086,-655.17 h60
  text "REV:" at 2377.5,-655.17 h60
  text ".PRJ_Number" at 3222,-655.17 h60
  text "BOARD #:" at 3767.5,-655.17 h60
  text "PCB VIEWED FROM BOTTOM SIDE" at 6244,-655.17 h60
  text "TEXAS INSTRUMENTS" at 902.5,-1063.84 h60
  text ".Print_Time" at 2167,-1063.84 h60
  text ".Print_Date" at 2896,-1063.84 h60
  text "GENERATED    :" at 3765.5,-1063.84 h60
  text ".plot_File_Name" at 5438.5,-1063.84 h60
  text "PLOT NAME =" at 6244,-1063.84 h60
M9 Title Sheet:
  drawing of 57 lines, arcs and shapes, not listed
  text "1" at 737.84,8037.5 h70
  text "2" at 3233.5,8037.5 h70
  text "3" at 5722.84,8037.5 h70
  text "4" at 8229.51,8037.5 h70
  text "5" at 10728.5,8037.5 h70
  text "6" at 13233.5,8037.5 h70
  text "A" at -418.5,6894.5 h70
  text "A" at 14381.5,6894.5 h70
  text "B" at -418.5,4514.5 h70
  text "B" at 14381.5,4514.5 h70
  text "C" at -418.5,2139.5 h70
  text "C" at 14381.5,2139.5 h70
  text "PROJECT TITLE:" at 11341.5,278.5 h45
  text ".PRJ_Title" at 11391.5,145.17 h70
  text "DESIGNED FOR:" at 11341.5,-22.5 h45
  text ".PRJ_Customer" at 11391.5,-162.5 h70
  text "D" at -418.5,-230.5 h70
  text "D" at 14381.5,-230.5 h70
  text "FILE NAME:" at 11341.5,-322.5 h45
  text ".PCB_File_Name_No_Path" at 11391.5,-442.5 h70
  text "Texas Instruments (TI) and/or its licensors do not warrant the accuracy or completeness of this specification" at 6372,-604.34 h45
  text "ENGINEER:" at 11341.5,-612.5 h45
  text "LAYOUT BY:" at 12846.5,-612.5 h45
  text "or any information contained therein. TI and/or its licensors do not warrant that this design will meet" at 6327.01,-717 h45
  text ".PRJ_Engineer" at 11391.5,-767.49 h70
  text ".PCB_Layout" at 12897,-767.49 h70
  text "the specifications, will be suitable for your application or fit for any particular purpose, or will operate in" at 6327.01,-829.67 h45
  text ".Layer_Name" at 575,-857.49 h60
  text "ALTIUM DESIGNER VERSION:" at 12846.5,-922.5 h45
  text "an implementation. TI and/or its licensors do not warrant that the design is production worthy. You should" at 6327.01,-942.33 h45
  text "completely validate and test your design implementation to confirm the system functionality for your application." at 6372,-1055 h45
  text ".print_Scale" at 11391.5,-1055.83 h70
  text ".Application_BuildNumber" at 12897,-1055.83 h70
  text "1" at 737.84,-1262.5 h70
  text "2" at 3233.5,-1262.5 h70
  text "3" at 5722.84,-1262.5 h70
  text "4" at 8229.51,-1262.5 h70
  text "5" at 10728.5,-1262.5 h70
  text "6" at 13233.5,-1262.5 h70
M10 Fab Notes:
  drawing of 185 lines, arcs and shapes, not listed
  text "DESIGN INFORMATION" at 12379.02,5911 h60
  text "MIN. TRACK WIDTH:" at 11734.46,5731 h60
  text "8" at 12830.7,5731 h60
  text "MIL" at 12985.46,5731 h60
  text "MIN. CLEARANCE:" at 11734.46,5599 h60
  text "0.2" at 12770.7,5599 h60
  text "mm" at 12985.46,5599 h60
  text "MIN. VIA PAD SIZE:" at 11734.46,5467 h60
  text "24" at 12800.71,5467 h60
  text "MIL" at 12985.46,5467 h60
  text "0.05mm (2MIL)" at 12429.46,5325.29 h60
  text "MINIMUM ANNULAR RING" at 11405.23,5321 h60
  text "EXTERNAL" at 13137.46,5321 h60
  text "PER" at 11605.23,5203 h60
  text "IPC-D-275 CLASS 2 LEVEL C" at 11825.23,5203 h60
  text "MIL, HOLES" at 13313.46,5090.71 h60
  text "+/-" at 12921,5090 h60
  text "+/-" at 13775,5090 h60
  text "REGISTRATION TOLERANCES:" at 11405.23,5085 h60
  text "METAL" at 12605,5085 h60
  text "5" at 13181.2,5085 h60
  text "3" at 14014.2,5085 h60
  text "MIL" at 14130.46,5085 h60
  text "MATERIAL:" at 11330.46,4875.54 h60
  text "FR-4 High Tg" at 12316.9,4735.21 h60
  text "FR-408" at 11751.46,4726.64 h60
  text "X" at 12163.46,4726.64 h60
  text "OTHER" at 13239.46,4726.64 h60
  text "62 MIL (1.6mm) +/-10%" at 12071.56,4563.92 h60
  text "THICKNESS:" at 11405.23,4559.64 h60
  text "X" at 11943.4,4559.64 h60
  text "OTHER" at 13356.46,4559.64 h60
  text "TOLERANCE:" at 11405.23,4401.64 h60
  text "X" at 12244.53,4401.64 h60
  text "ANSI IPC-6012 TYPE 3 CLASS 2" at 12431.48,4401.64 h60
  text "4.1m trace with 7m spacing should have 100 ohm impedance" at 6691,4275 h80
  text "OTHER +/-" at 12431.46,4245.64 h60
  text "BOW & TWIST:" at 11405.23,4088.64 h60
  text "X" at 12244.53,4088.64 h60
  text "ANSI IPC-6012 TYPE 3 CLASS 2" at 12431.48,4088.64 h60
  text "5.4m outer traces should have 50 ohm impedance" at 6672,3972 h80
  text "OTHER +/-" at 12431.46,3930.13 h60
  text "DRILLING:" at 11330.46,3791.64 h60
  text "REFERENCE:" at 11405.23,3674.64 h60
  text "X" at 12053.46,3674.64 h60
  text "AS SHOWN" at 12240.46,3674.64 h60
  text "X" at 12954.46,3674.64 h60
  text "NC_DRILL FILES" at 13091.46,3674.64 h60
  text "PTH MIN COPPER THICKNESS:" at 11405.23,3516.64 h60
  text "X" at 12755.46,3516.64 h60
  text "1MIL" at 12892.46,3516.64 h60
  text "OTHER" at 13389.46,3516.64 h60
  text "BOARD FINISH:" at 11330.46,3357.64 h60
  text "SILKSCREEN:" at 11485.68,3239.64 h60
  text "X" at 12434.46,3239.64 h60
  text "TOP" at 12560.46,3239.64 h60
  text "X" at 12944.46,3239.64 h60
  text "BOTTOM" at 13071.46,3239.64 h60
  text "SILKSCREEN COLOR:" at 11485.68,3072.64 h60
  text "X" at 12433.42,3072.64 h60
  text "WHITE" at 12560.46,3072.64 h60
  text "OTHER" at 13071.46,3072.64 h60
  text "SOLDER RESIST COLOR:" at 11485.68,2902.64 h60
  text "X" at 12053.42,2743.44 h60
  text "GREEN" at 12180.46,2743.44 h60
  text "BLUE" at 12771.46,2743.44 h60
  text "OTHER" at 13309.46,2743.44 h60
  text "IMMERSION GOLD (ENIG)" at 12391.46,2554.92 h60
  text "ENEPIG" at 13729,2551.64 h60
  text "SURFACE FINISH:" at 11330.46,2550.64 h60
  text "X" at 12204.51,2550.64 h60
  text "IMM. TIN/SILVER OR EQUIV" at 11660,2393.64 h60
  text "OTHER" at 13091.46,2393.64 h60
  text "ARRAY/PANEL:" at 11330.46,2214.64 h60
  text "CUT AND TRIM PER MECH LAYER 1" at 12391.46,2210.35 h60
  text "N.C. ROUTE" at 12391.46,2058.64 h60
  text "X" at 13070.46,2058.64 h60
  text "V. SCORE" at 13257.46,2058.64 h60
  text "CERTIFICATION:" at 11330.46,1921.64 h60
  text "MATERIALS AND WORKMANSHIP FOR ALL PCBS" at 12055.46,1921.64 h60
  text "TO MEET OR EXCEED THE REQUIREMENTS OF:" at 12055.46,1823.64 h60
  text "X" at 11681.96,1687.13 h60
  text "ANSI IPC-A-600F CLASS ->" at 11820.96,1687.13 h60
  text "X" at 13460.02,1687.13 h60
  text "2" at 13578.96,1687.14 h60
  text "1" at 13263.96,1685.64 h60
  text "3" at 13932.96,1685.64 h60
  text "X" at 11684.02,1527.64 h60
  text "UL 94V-0" at 11820.96,1527.64 h60
  text "X" at 12496.02,1527.64 h60
  text "RoHS" at 12632.96,1527.64 h60
  text "OTHER" at 13277.36,1527.64 h60
  text "PER ORDER" at 13674.42,1527.64 h60
  text "ADDITIONAL REQUIREMENTS:" at 11330.46,1386.64 h60
  text "MICROSECTION:" at 11405.23,1271.64 h60
  text "YES" at 12310.96,1271.64 h60
  text "REQUIRED" at 13172.46,1115.49 h60
  text "BARE BOARD ELEC. TEST:" at 11405.23,1112.64 h60
  text "NONE" at 12710.96,1112.64 h60
  text "X" at 13045.46,1112.64 h60
  text "PER ORDER" at 13764.46,1112.64 h60
  text "MANUFACTURER'S UL:" at 11405.23,955.64 h60
  text "RAIL" at 12570.96,951.35 h60
  text "METAL" at 13062.77,951.35 h60
  text "X" at 13438,951 h60
  text "SILK" at 13574.46,951.35 h60
  text ".Layer_Name" at 575,-857.49 h60
M11 Gerber Information:
  lines w10: -294,-929.17 6306,-929.17 ; -294,-725.83 6308,-725.83 ; -294,-522.5 -294,-1132.5 3711,-1132.5 6308,-1132.5 6308,-522.5 ; -293.5,-522.5 -293.5,-1132.5 1282,-1132.5 ; 2171,-1132.5 2171,-522.5 ; 3438,-725.83 3438,-522.5 ; 4278,-725.83 4278,-522.5 ; 4900,-1139 4900,-936.17
  text "ALL ARTWORK VIEWED FROM TOP SIDE" at -230.5,-654.67 h60
  text "BOARD #:" at 2246,-654.67 h60
  text ".PRJ_Number" at 2791.5,-654.67 h60
  text "REV:" at 3636,-654.67 h60
  text ".PCB_Rev" at 3927.5,-654.67 h60
  text "SVN REV:" at 4474,-654.67 h60
  text ".VersionControl_RevNumber" at 4980,-654.67 h60
  text "LAYER NAME =" at -230.5,-857.49 h60
  text "PLOT NAME =" at -230.5,-1063.34 h60
  text ".plot_File_Name" at 575,-1063.34 h60
  text "GENERATED    :" at 2248,-1063.34 h60
  text ".Print_Date" at 3117.5,-1063.34 h60
  text ".Print_Time" at 3846.5,-1063.34 h60
  text "TEXAS INSTRUMENTS" at 5111,-1063.34 h60
M12 Stackup:
  drawing of 295 lines, arcs and shapes, not listed
  text "Layer" at 9758,7831 h60
  text "Name" at 10167.91,7831 h60
  text "Material" at 11097.66,7831 h60
  text "Thickness" at 11957.42,7831 h60
  text "Constant" at 12607.26,7831 h60
  text "Board Layer Stack" at 13177.12,7831 h60
  text "1" at 9758,7711 h60
  text "Top Overlay" at 10167.91,7711 h60
  text "2" at 9758,7591 h60
  text "Top Solder" at 10167.91,7591 h60
  text "Solder Resist" at 11097.66,7591 h60
  text "0.40mil" at 11957.42,7591 h60
  text "3.5" at 12607.26,7591 h60
  text "3" at 9758,7471 h60
  text "Top Layer" at 10167.91,7471 h60
  text "Copper" at 11097.66,7471 h60
  text "1.40mil" at 11957.42,7471 h60
  text "4" at 9758,7351 h60
  text "Dielectric1" at 10167.91,7351 h60
  text "FR-4" at 11097.66,7351 h60
  text "3.50mil" at 11957.42,7351 h60
  text "4.8" at 12607.26,7351 h60
  text "5" at 9758,7231 h60
  text "Mid-Layer 1" at 10167.91,7231 h60
  text "Copper" at 11097.66,7231 h60
  text "1.40mil" at 11957.42,7231 h60
  text "6" at 9758,7111 h60
  text "Dielectric2" at 10167.91,7111 h60
  text "FR-4" at 11097.66,7111 h60
  text "47.60mil" at 11957.42,7111 h60
  text "4.8" at 12607.26,7111 h60
  text "7" at 9758,6991 h60
  text "Mid-Layer 2" at 10167.91,6991 h60
  text "Copper" at 11097.66,6991 h60
  text "1.40mil" at 11957.42,6991 h60
  text "8" at 9758,6871 h60
  text "Dielectric3" at 10167.91,6871 h60
  text "FR-4" at 11097.66,6871 h60
  text "3.50mil" at 11957.42,6871 h60
  text "4.8" at 12607.26,6871 h60
  text "9" at 9758,6751 h60
  text "Bottom Layer" at 10167.91,6751 h60
  text "Copper" at 11097.66,6751 h60
  text "1.40mil" at 11957.42,6751 h60
  text "10" at 9758,6631 h60
  text "Bottom Solder" at 10167.91,6631 h60
  text "Solder Resist" at 11097.66,6631 h60
  text "0.40mil" at 11957.42,6631 h60
  text "3.5" at 12607.26,6631 h60
  text "11" at 9758,6511 h60
  text "Bottom Overlay" at 10167.91,6511 h60
  text ".Layer_Name" at 575,-857.49 h60
M13 Component Bodies Top:
  text ".Layer_Name" at 575,-857.49 h60
M14 Component Bodies Bottom:
  text ".Layer_Name" at 575,-857.49 h60
M15 Courtyards Top:
  text ".Layer_Name" at 575,-857.49 h60
M16 Courtyards Bottom:
  text ".Layer_Name" at 575,-857.49 h60
Drill Drawing:
  drawing of 182 lines, arcs and shapes, not listed
  text "Symbol" at 6718.7,7748.88 h94.86
  text "Quantity" at 7139.86,7748.88 h94.86
  text "Finished Hole Size" at 7602.45,7748.88 h94.86
  text "Plated" at 8466.55,7748.88 h94.86
  text "Hole Type" at 8833.09,7748.88 h94.86
  text "4" at 7139.86,7560.14 h79.05
  text "57.09mil (1.450mm)" at 7602.45,7560.14 h79.05
  text "NPTH" at 8466.55,7560.14 h79.05
  text "Round" at 8833.09,7560.14 h79.05
  text "2" at 7139.86,7371.39 h79.05
  text "137.80mil (3.500mm)" at 7602.45,7371.39 h79.05
  text "NPTH" at 8466.55,7371.39 h79.05
  text "Round" at 8833.09,7371.39 h79.05
  text "40" at 7139.86,7182.65 h79.05
  text "7.87mil (0.200mm)" at 7602.45,7182.65 h79.05
  text "PTH" at 8466.55,7182.65 h79.05
  text "Round" at 8833.09,7182.65 h79.05
  text "386" at 7139.86,6993.9 h79.05
  text "10.00mil (0.254mm)" at 7602.45,6993.9 h79.05
  text "PTH" at 8466.55,6993.9 h79.05
  text "Round" at 8833.09,6993.9 h79.05
  text "2" at 7139.86,6805.16 h79.05
  text "30.00mil (0.762mm)" at 7602.45,6805.16 h79.05
  text "PTH" at 8466.55,6805.16 h79.05
  text "Round" at 8833.09,6805.16 h79.05
  text "12" at 7139.86,6616.42 h79.05
  text "35.04mil (0.890mm)" at 7602.45,6616.42 h79.05
  text "PTH" at 8466.55,6616.42 h79.05
  text "Round" at 8833.09,6616.42 h79.05
  text "1" at 7139.86,6427.67 h79.05
  text "37.99mil (0.965mm)" at 7602.45,6427.67 h79.05
  text "PTH" at 8466.55,6427.67 h79.05
  text "Round" at 8833.09,6427.67 h79.05
  text "112" at 7139.86,6238.93 h79.05
  text "40.00mil (1.016mm)" at 7602.45,6238.93 h79.05
  text "PTH" at 8466.55,6238.93 h79.05
  text "Round" at 8833.09,6238.93 h79.05
  text "2" at 7139.86,6050.18 h79.05
  text "40.16mil (1.020mm)" at 7602.45,6050.18 h79.05
  text "PTH" at 8466.55,6050.18 h79.05
  text "Round" at 8833.09,6050.18 h79.05
  text "6" at 7139.86,5861.44 h79.05
  text "59.06mil (1.500mm)" at 7602.45,5861.44 h79.05
  text "PTH" at 8466.55,5861.44 h79.05
  text "Round" at 8833.09,5861.44 h79.05
  text "2" at 7139.86,5672.7 h79.05
  text "61.81mil (1.570mm)" at 7602.45,5672.7 h79.05
  text "PTH" at 8466.55,5672.7 h79.05
  text "Round" at 8833.09,5672.7 h79.05
  text "24" at 7139.86,5483.95 h79.05
  text "62.99mil (1.600mm)" at 7602.45,5483.95 h79.05
  text "PTH" at 8466.55,5483.95 h79.05
  text "Round" at 8833.09,5483.95 h79.05
  text "3" at 7139.86,5295.21 h79.05
  text "165.00mil (4.191mm)" at 7602.45,5295.21 h79.05
  text "PTH" at 8466.55,5295.21 h79.05
  text "Round" at 8833.09,5295.21 h79.05
  text "2" at 7139.86,5106.46 h79.05
  text "29.92mil (0.760mm)" at 7602.45,5106.46 h79.05
  text "PTH" at 8466.55,5106.46 h79.05
  text "Slot" at 8833.09,5106.46 h79.05
  text "1" at 7139.86,4917.72 h79.05
  text "39.76mil (1.010mm)" at 7602.45,4917.72 h79.05
  text "PTH" at 8466.55,4917.72 h79.05
  text "Slot" at 8833.09,4917.72 h79.05
  text "599 Total" at 7139.86,4728.98 h79.05
  text ".Layer_Name" at 575,-857.49 h60

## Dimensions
10,3146 to 3727,3193 on M2 Board Dimensions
